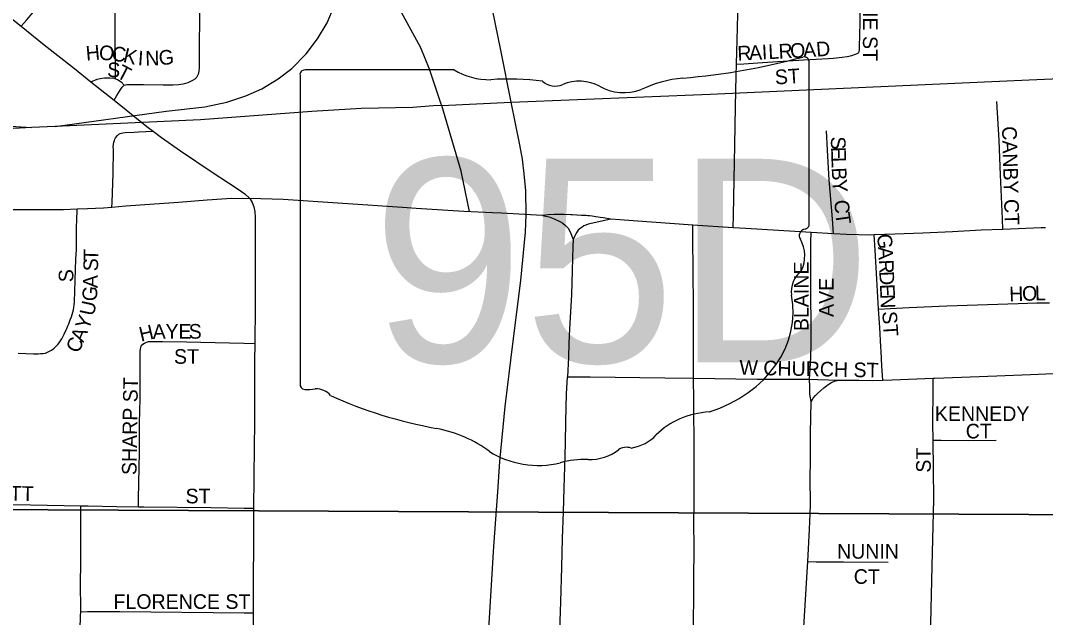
# Model space of a CAD drawing. Extents: x -9.1 to 34, y -3.1 to 22.
# Drawn here: x 4.437 to 5.101, y 19.706 to 20.093 of the extents above; entities that cross this region are included whole.
import ezdxf

# ---------------------------------------------------------------- set-up
doc = ezdxf.new("R2010")
doc.units = 0
for name, color, linetype in [('GM_X_City_Street', 7, 'Continuous'), ('GM_X_City_Street_Text', 7, 'Continuous'), ('GM_X_Rail_Line', 7, 'Continuous'), ('GM_X_Section', 7, 'Continuous'), ('GM_X_State_Location', 7, 'Continuous'), ('GM_X_State_Route', 7, 'Continuous'), ('GM_X_State_Shield', 7, 'Continuous')]:
    doc.layers.add(name, color=color, linetype=linetype)

msp = doc.modelspace()

# ---------------------------------------------------------------- linework, layer by layer
at = {"layer": 'GM_X_City_Street'}
for points in [[(4.49874, 20.05516), (4.4988, 20.05841), (4.49887, 20.0614), (4.49858, 20.08324), (4.49882, 20.11749), (4.499, 20.18602), (4.49938, 20.25459), (4.49955, 20.27638), (4.49959, 20.28149)], [(4.5514, 20.05627), (4.55222, 20.05754), (4.55273, 20.05884), (4.55302, 20.06023), (4.55314, 20.06211), (4.55321, 20.06449), (4.55321, 20.06828), (4.55329, 20.07756), (4.55336, 20.09304), (4.55365, 20.12694), (4.55371, 20.15158), (4.55374, 20.17483), (4.55381, 20.2012), (4.55388, 20.22423), (4.55393, 20.24258), (4.55398, 20.25718), (4.55403, 20.27252), (4.55406, 20.28039)], [(4.4377, 20.08918), (4.44141, 20.09336), (4.44584, 20.09857), (4.44801, 20.10125), (4.4496, 20.10326), (4.45032, 20.10424), (4.45095, 20.10527), (4.45151, 20.10661), (4.45187, 20.1081), (4.45213, 20.11007), (4.45227, 20.11208), (4.45238, 20.11518), (4.45218, 20.12445), (4.45221, 20.14299), (4.45209, 20.15844), (4.45209, 20.17698), (4.45237, 20.19552), (4.45234, 20.20788), (4.45239, 20.21714), (4.45234, 20.22331)], [(4.90088, 20.06455), (4.90141, 20.08805), (4.90184, 20.10654), (4.90227, 20.12594)], [(4.97985, 20.07208), (4.98005, 20.0723), (4.98016, 20.07257), (4.98022, 20.07285), (4.98033, 20.07384), (4.98045, 20.07584), (4.98084, 20.09149), (4.98078, 20.09461), (4.98088, 20.10402), (4.98088, 20.11974), (4.98088, 20.12615)], [(4.90088, 20.06455), (4.9056, 20.06485), (4.91766, 20.06563), (4.94412, 20.06735), (4.95231, 20.06783), (4.96028, 20.06834), (4.96356, 20.06856), (4.96928, 20.06914), (4.97242, 20.06965), (4.97536, 20.07032), (4.97788, 20.07113), (4.97894, 20.07157), (4.97948, 20.07184), (4.97985, 20.07208)], [(4.89865, 19.9587), (4.89882, 19.96686), (4.89927, 19.98977), (4.89972, 20.01233), (4.90022, 20.03699), (4.90062, 20.05718), (4.90088, 20.06455)], [(4.4829, 20.05327), (4.48694, 20.05486), (4.48897, 20.05536), (4.49165, 20.05568), (4.49525, 20.05581), (4.49779, 20.05549), (4.49874, 20.05516)], [(4.49795, 20.04136), (4.49976, 20.04439), (4.50186, 20.04788), (4.50318, 20.04978), (4.50451, 20.05106)], [(4.49874, 20.05516), (4.50014, 20.05467), (4.50242, 20.05315), (4.50451, 20.05106)], [(4.50451, 20.05106), (4.50611, 20.05137), (4.50864, 20.0515), (4.51137, 20.05144), (4.51687, 20.05146), (4.52959, 20.05131), (4.53619, 20.05132), (4.53957, 20.05151), (4.54267, 20.05196), (4.54439, 20.05237), (4.54585, 20.05277), (4.54759, 20.05351), (4.54889, 20.05424), (4.55032, 20.05522), (4.5514, 20.05627)], [(5.07313, 19.95761), (5.07289, 19.96456), (5.07257, 19.97405), (5.0716, 19.99301), (5.07076, 20.01514), (5.0694, 20.04044)], [(4.49882, 20.01683), (4.50008, 20.01845), (4.50097, 20.01924), (4.50195, 20.01976), (4.50359, 20.02013), (4.50499, 20.0203), (4.51087, 20.02062), (4.51368, 20.02075), (4.52329, 20.02122)], [(4.96364, 19.9548), (4.96287, 19.96441), (4.96084, 19.98979), (4.95962, 20.00885), (4.95896, 20.02155)], [(4.4965, 19.97212), (4.49661, 19.97498), (4.49733, 19.99375), (4.49742, 20.00946), (4.49741, 20.01101), (4.49756, 20.01258), (4.49782, 20.01421), (4.49808, 20.01525), (4.49834, 20.01609), (4.49882, 20.01683)], [(4.45746, 19.87949), (4.4589, 19.88059), (4.4603, 19.88178), (4.46139, 19.88298), (4.46232, 19.88409), (4.4632, 19.88535), (4.46409, 19.88674), (4.4656, 19.88971), (4.46687, 19.89249), (4.46729, 19.8935), (4.46803, 19.89521), (4.46854, 19.89645), (4.46905, 19.89772), (4.46955, 19.89906), (4.47027, 19.90104), (4.47069, 19.90249), (4.47118, 19.90405), (4.47157, 19.90561), (4.47187, 19.90706), (4.47214, 19.90877), (4.47229, 19.91062), (4.4732, 19.93835), (4.47358, 19.94451), (4.47366, 19.95996), (4.47376, 19.96305), (4.47404, 19.97087)], [(4.7753, 19.96664), (4.77956, 19.96565), (4.78267, 19.96448), (4.78644, 19.96282), (4.78832, 19.96172), (4.79021, 19.96025), (4.79179, 19.95838), (4.79307, 19.95601), (4.79505, 19.95098)], [(4.81951, 19.96433), (4.80472, 19.96095), (4.80328, 19.96044), (4.80205, 19.95996), (4.80087, 19.95917), (4.79958, 19.95818), (4.7984, 19.9571), (4.79742, 19.95581), (4.79653, 19.95433), (4.79584, 19.95295), (4.79505, 19.95098)], [(4.87298, 19.90525), (4.87297, 19.90841), (4.87255, 19.95228), (4.87247, 19.96031)], [(4.79505, 19.95098), (4.79487, 19.94665), (4.79448, 19.93093), (4.79389, 19.91524), (4.79279, 19.89328), (4.79235, 19.88384), (4.79196, 19.87456), (4.79138, 19.86205)], [(4.94809, 19.86072), (4.94878, 19.87074), (4.94892, 19.87491), (4.9492, 19.88357), (4.94917, 19.88665), (4.94891, 19.92407), (4.949, 19.94932), (4.94902, 19.95567)], [(4.99274, 19.90598), (4.99153, 19.9254), (4.99051, 19.94411), (4.98996, 19.95402)], [(4.87294, 19.8612), (4.87306, 19.87726), (4.87298, 19.90525)], [(4.99274, 19.90598), (5.00021, 19.90641), (5.01245, 19.90712), (5.03697, 19.90804), (5.08306, 19.90961), (5.09523, 19.90999), (5.10347, 19.91014)], [(4.99547, 19.86005), (4.99529, 19.8631), (4.99492, 19.86934), (4.99444, 19.87852), (4.99426, 19.88158), (4.99348, 19.89402), (4.99274, 19.90598)], [(4.51553, 19.88206), (4.51654, 19.88322), (4.51762, 19.88399), (4.51886, 19.88454), (4.5201, 19.88492), (4.52126, 19.88508), (4.52281, 19.88506), (4.52482, 19.88504), (4.52915, 19.885), (4.54484, 19.88487), (4.56339, 19.88445), (4.58194, 19.88399), (4.58892, 19.88383)], [(4.43592, 19.87741), (4.44582, 19.87712), (4.44887, 19.8771), (4.45033, 19.87715), (4.45191, 19.87728), (4.45343, 19.87754), (4.45483, 19.87803), (4.45618, 19.87867), (4.45746, 19.87949)], [(4.51371, 19.778), (4.5138, 19.78312), (4.51431, 19.81354), (4.51435, 19.81671), (4.5144, 19.81977), (4.51436, 19.82894), (4.51446, 19.83181), (4.51446, 19.83468), (4.51454, 19.8377), (4.51485, 19.85019), (4.51482, 19.87485), (4.51482, 19.87617), (4.51484, 19.87826), (4.51507, 19.8802), (4.51553, 19.88206)], [(4.78619, 19.68761), (4.78632, 19.69165), (4.78706, 19.71644), (4.78765, 19.73881), (4.78821, 19.75737), (4.78874, 19.77472), (4.7892, 19.79012), (4.78961, 19.80392), (4.79002, 19.81913), (4.79039, 19.83313), (4.79084, 19.85111), (4.79138, 19.86205)], [(4.79138, 19.86205), (4.80615, 19.86216), (4.85438, 19.86139), (4.87294, 19.8612)], [(4.87294, 19.8612), (4.91413, 19.86066), (4.94599, 19.86072), (4.94809, 19.86072)], [(4.87302, 19.69196), (4.87302, 19.6932), (4.87323, 19.73032), (4.87331, 19.752), (4.87324, 19.76754), (4.87343, 19.77996), (4.87337, 19.78602), (4.87349, 19.81334), (4.87311, 19.84699), (4.87294, 19.8612)], [(4.94809, 19.86072), (4.9534, 19.86048), (4.96708, 19.86003)], [(4.9492, 19.84603), (4.94863, 19.84861), (4.94834, 19.85098), (4.94822, 19.85565), (4.94809, 19.86072)], [(5.02799, 19.82108), (5.02793, 19.83222), (5.02804, 19.85377), (5.02807, 19.86123)], [(5.02624, 19.68796), (5.0266, 19.70234), (5.02747, 19.73956), (5.02846, 19.78295), (5.02799, 19.82108)], [(5.02799, 19.82108), (5.03331, 19.82104), (5.0512, 19.82088), (5.06887, 19.82114)], [(4.36566, 19.78066), (4.38924, 19.78031), (4.41939, 19.77962), (4.44389, 19.77921), (4.47645, 19.7787)], [(4.47629, 19.70998), (4.4764, 19.71677), (4.47619, 19.72297), (4.47622, 19.73232), (4.47643, 19.73747), (4.47634, 19.74164), (4.4763, 19.76335), (4.47637, 19.76957), (4.47645, 19.7787)], [(4.47645, 19.7787), (4.48105, 19.77864), (4.49937, 19.77826), (4.51371, 19.778)], [(4.51371, 19.778), (4.51726, 19.77793), (4.56053, 19.77749), (4.58219, 19.77715), (4.58822, 19.77706)], [(4.94687, 19.74247), (4.9524, 19.74243), (4.97004, 19.74233), (4.99886, 19.7422)], [(4.47586, 19.68608), (4.4759, 19.69213), (4.47604, 19.69844), (4.47625, 19.70744), (4.47629, 19.70998)], [(4.47629, 19.70998), (4.48072, 19.71009), (4.48979, 19.71013), (4.50163, 19.7101), (4.58211, 19.70938), (4.58788, 19.70933)]]:
    msp.add_lwpolyline(points, dxfattribs=at)
at = {"layer": 'GM_X_Rail_Line'}
for points in [[(4.75491, 20.03998), (4.74815, 20.07376), (4.74114, 20.10871), (4.73789, 20.12443), (4.7349, 20.14029), (4.73321, 20.15172), (4.73217, 20.1612), (4.73113, 20.17329), (4.73074, 20.18758), (4.73087, 20.20382), (4.73178, 20.27568), (4.73412, 20.38846), (4.73899, 20.64696), (4.73945, 20.75234), (4.7401, 20.80691), (4.74107, 20.89157), (4.74116, 20.9)], [(4.4598, 20.02426), (4.53171, 20.0341), (4.55655, 20.03704), (4.57092, 20.04007), (4.58325, 20.04408), (4.59361, 20.04868), (4.60417, 20.05513), (4.61298, 20.06178), (4.62217, 20.07136), (4.6295, 20.08095), (4.63576, 20.09141), (4.64036, 20.10217), (4.64339, 20.11156), (4.64564, 20.12349), (4.64613, 20.13796), (4.64525, 20.14872), (4.64251, 20.16368), (4.6386, 20.17366), (4.634, 20.18373), (4.62911, 20.19263), (4.61029, 20.22782), (4.54232, 20.35069), (4.53176, 20.37042), (4.5167, 20.4033)], [(4.7097, 20.03871), (4.70209, 20.06128), (4.69638, 20.07528), (4.61143, 20.2311)], [(2.6, 20.20616), (2.61878, 20.20477), (2.65021, 20.20366), (2.67105, 20.20276), (2.70793, 20.19875), (3.62422, 20.09412), (3.99829, 20.05166), (4.19407, 20.02982), (4.21899, 20.02788), (4.24227, 20.02625), (4.29308, 20.02562), (4.35791, 20.026), (4.38531, 20.02687), (4.40008, 20.0265), (4.44452, 20.02352)], [(4.75491, 20.03998), (4.88383, 20.04522), (5.08049, 20.05405), (5.19819, 20.05912), (5.37213, 20.0668), (5.43128, 20.06935)], [(4.7044, 20.03755), (4.69135, 20.03665), (4.6579, 20.03587), (4.62581, 20.03402), (4.55375, 20.02867), (4.4598, 20.02426)], [(4.70996, 20.03794), (4.7044, 20.03755)], [(4.70996, 20.03794), (4.7097, 20.03871)], [(4.70996, 20.03794), (4.75491, 20.03998)], [(4.72803, 19.9692), (4.72264, 19.9953), (4.70996, 20.03794)], [(4.76465, 19.96727), (4.76452, 19.98255), (4.76336, 19.99359), (4.76219, 20.0032), (4.76063, 20.01243), (4.75491, 20.03998)], [(4.4598, 20.02426), (4.44452, 20.02352)], [(4.44452, 20.02352), (4.42483, 20.02258)], [(4.78778, 19.09094), (4.76193, 19.17487), (4.7375, 19.25556), (4.73373, 19.26843), (4.73113, 19.27856), (4.7284, 19.29065), (4.72658, 19.30156), (4.7245, 19.31481), (4.7236, 19.32365), (4.72241, 19.33388), (4.72204, 19.3499), (4.72178, 19.36367), (4.7223, 19.37848), (4.72399, 19.41031), (4.73308, 19.56935), (4.73945, 19.68097), (4.74361, 19.75217), (4.7462, 19.78777), (4.74763, 19.80726), (4.75114, 19.843), (4.75595, 19.88354), (4.76128, 19.92446), (4.76426, 19.95591), (4.76465, 19.96727)]]:
    msp.add_lwpolyline(points, dxfattribs=at)
at = {"layer": 'GM_X_Section'}
for points in [[(4.22892, 20.78268), (5.2279, 20.77322), (5.226, 19.77229), (4.2285, 19.77719)], [(4.2285, 19.77719), (5.226, 19.77229), (5.22068, 18.771), (4.22542, 18.77097)]]:
    msp.add_lwpolyline(points, close=True, dxfattribs=at)
at = {"layer": 'GM_X_State_Route'}
for points in [[(4.23107, 20.25518), (4.25901, 20.23288), (4.29774, 20.20173), (4.35591, 20.15507), (4.37889, 20.13658), (4.414, 20.10833), (4.4377, 20.08918), (4.45266, 20.07709), (4.47222, 20.06172), (4.4829, 20.05327), (4.49795, 20.04136), (4.50576, 20.03497), (4.51271, 20.02947), (4.52002, 20.0237), (4.52329, 20.02122), (4.52859, 20.01721), (4.541, 20.00846), (4.56139, 19.9947), (4.57197, 19.98778), (4.57827, 19.98368), (4.58251, 19.98056), (4.58588, 19.97764)], [(4.3665, 19.97125), (4.3675, 19.97124), (4.37512, 19.97115), (4.43089, 19.97052), (4.43696, 19.9705), (4.44585, 19.97047), (4.46523, 19.97051), (4.47404, 19.97087), (4.48078, 19.97116), (4.49113, 19.97166), (4.4965, 19.97212), (4.50558, 19.9729), (4.53965, 19.97525), (4.55824, 19.97671), (4.57384, 19.97787), (4.58588, 19.97764)], [(4.58588, 19.97764), (4.58734, 19.97496), (4.58841, 19.97222), (4.589, 19.96915), (4.58926, 19.9653), (4.58925, 19.9584), (4.58924, 19.94675), (4.58917, 19.9065), (4.58893, 19.8848), (4.58892, 19.88383), (4.58875, 19.87237), (4.5888, 19.86936), (4.58878, 19.86134), (4.58876, 19.84897), (4.58875, 19.83996), (4.58874, 19.83233), (4.58851, 19.81686), (4.58822, 19.77706), (4.58813, 19.76405), (4.58793, 19.72073), (4.58788, 19.70933), (4.58787, 19.70518), (4.58772, 19.68235)], [(4.68457, 19.97176), (4.60739, 19.97688), (4.58588, 19.97764)], [(4.79445, 19.96699), (4.79347, 19.96703), (4.78915, 19.9672), (4.78278, 19.9672), (4.77884, 19.96697), (4.7753, 19.96664), (4.76755, 19.96706), (4.74865, 19.96808), (4.74282, 19.96826), (4.72433, 19.96924), (4.69354, 19.97117), (4.68457, 19.97176)], [(5.10086, 19.95871), (5.09809, 19.95866), (5.07313, 19.95761), (5.05922, 19.95702), (5.04061, 19.95598), (5.02149, 19.95515), (5.00321, 19.95446), (4.98996, 19.95402), (4.98762, 19.95394), (4.97198, 19.9543), (4.96364, 19.9548), (4.94902, 19.95567), (4.90682, 19.95819), (4.89865, 19.9587), (4.87247, 19.96031), (4.8338, 19.96314), (4.82527, 19.96377), (4.81951, 19.96433), (4.81458, 19.96505), (4.81253, 19.96543), (4.80981, 19.9658), (4.80736, 19.96614), (4.80565, 19.96634), (4.80459, 19.96646), (4.80322, 19.9666), (4.80056, 19.96671), (4.79445, 19.96699)], [(4.96708, 19.86003), (4.96844, 19.85993), (4.98007, 19.8599), (4.98913, 19.85984), (4.99547, 19.86005), (5.00153, 19.86024), (5.02807, 19.86123), (5.02924, 19.86127), (5.06928, 19.86271), (5.09104, 19.86356), (5.10596, 19.86424), (5.12191, 19.86496), (5.18634, 19.86778), (5.19618, 19.86822), (5.21393, 19.86893), (5.27092, 19.87124), (5.27826, 19.87168)], [(4.9492, 19.84603), (4.9505, 19.84825), (4.95192, 19.85014), (4.95317, 19.8513), (4.95546, 19.85326), (4.95733, 19.85495), (4.95906, 19.85637), (4.96011, 19.8571), (4.96091, 19.85765), (4.9619, 19.85826), (4.96322, 19.85892), (4.96492, 19.85959), (4.96708, 19.86003)], [(4.94515, 19.6888), (4.94459, 19.69187), (4.94429, 19.69443), (4.94421, 19.69656), (4.94687, 19.74247), (4.94807, 19.76318), (4.94862, 19.77878), (4.9484, 19.79752), (4.94862, 19.80683), (4.94861, 19.82556), (4.9492, 19.84603)]]:
    msp.add_lwpolyline(points, dxfattribs=at)
at = {"layer": 'GM_X_State_Shield'}
for p, q in [((4.94787, 19.96123), (4.94787, 20.06592)), ((4.61828, 20.05752), (4.61828, 19.8574)), ((4.71805, 20.06096), (4.62153, 20.06096)), ((4.94783, 19.96126), (4.94787, 19.96123))]:
    msp.add_line(p, q, dxfattribs=at)
for centre, major_axis, start_param, end_param in [((4.83046, 20.33379), (0.34952, 0), 4.814394, 5.042369), ((4.94421, 20.06635), (0.00367, 0), 6.141152, 7.989035), ((4.62206, 20.05794), (0.00382, 0), 1.712693, 3.28349), ((4.74103, 20.08419), (0.03703, 0), 4.042523, 4.731795), ((4.75331, 19.94861), (0.13295, 0), 1.404758, 1.657858), ((4.7835, 20.05898), (0.01068, 0), 3.836095, 5.185415), ((4.79918, 20.03585), (0.02221, 0), 0.950623, 2.079405), ((4.82785, 20.06757), (0.02672, 0), 4.081561, 5.145723), ((4.87505, 19.99984), (0.07032, 0), 1.699011, 2.107814), ((4.94702, 19.95355), (0.00568, 0), 1.883978, 3.671073), ((4.94395, 19.96083), (0.00393, 0), 5.05454, 6.418171), ((4.91089, 19.94031), (0.03409, 0), 5.934695, 6.695948), ((4.96101, 19.91742), (0.0248, 0), 2.387724, 3.262537), ((4.85004, 19.90411), (0.08742, 0), 5.101752, 6.440018), ((4.62209, 19.85696), (0.00385, 0), 3.00124, 4.508301), ((4.62268, 19.87743), (0.0294, 0), 4.665946, 4.897461), ((4.62869, 19.84585), (0.0106, 0), 0.519207, 1.627899), ((4.76252, 20.02565), (0.2524, 0), 4.195997, 4.488961), ((4.8869, 19.80121), (0.04788, 0), 1.647645, 2.488434), ((4.68727, 19.76749), (0.07897, 0), 0.823519, 1.323587), ((4.82624, 19.838), (0.02824, 0), 4.937069, 5.64225), ((4.77268, 19.84486), (0.05011, 0), 4.026481, 4.996735), ((4.80529, 19.82987), (0.0267, 0), 4.691044, 5.507374), ((4.82945, 19.81049), (0.00752, 0), 1.147584, 2.315152), ((4.80163, 19.77567), (0.04118, 0), 1.495662, 1.94098)]:
    msp.add_ellipse(centre, major_axis=major_axis, ratio=0.8, start_param=start_param, end_param=end_param, dxfattribs=at)

# ---------------------------------------------------------------- texts
at = {"layer": 'GM_X_City_Street_Text'}
for s, height, rotation, p in [('ERIE ST', 0.00947, 270, (4.98263, 20.11592)), ('H', 0.00947, 5.09944, (4.47999, 20.06686)), ('O', 0.00947, 355.29625, (4.48786, 20.0676)), ('A', 0.00947, 2.83454, (4.90909, 20.06724)), ('I', 0.00947, 2.84276, (4.91741, 20.06765)), ('L', 0.00947, 2.81466, (4.92157, 20.06786)), ('R', 0.00947, 2.83186, (4.92823, 20.06818)), ('O', 0.00947, 2.82093, (4.93572, 20.06856)), ('A', 0.00947, 3.17297, (4.94411, 20.06897)), ('D', 0.00947, 4.83643, (4.95273, 20.06945)), ('C', 0.00947, 353.60082, (4.49609, 20.06692)), ('K', 0.00947, 346.40905, (4.50324, 20.06614)), ('I', 0.00947, 356.02956, (4.51305, 20.06392)), ('N', 0.00947, 1.50299, (4.51819, 20.06361)), ('G', 0.00947, 5.48292, (4.52724, 20.06387)), ('R', 0.00947, 2.81874, (4.90159, 20.06687)), ('S', 0.00947, 357.07482, (4.49322, 20.05642)), ('T', 0.00947, 332.66519, (4.49885, 20.05635)), ('ST', 0.00947, 3.57463, (4.92592, 20.05144)), ('CANBY CT', 0.00947, 271.63302, (5.07263, 20.0243)), ('S', 0.00947, 271.77627, (4.96179, 20.01764)), ('E', 0.00947, 271.74896, (4.962, 20.01098)), ('L', 0.00947, 271.76405, (4.9622, 20.00431)), ('B', 0.00947, 272.35658, (4.96241, 19.99754)), ('Y', 0.00947, 274.71212, (4.96275, 19.98962)), ('C', 0.00947, 271.23851, (4.96429, 19.9767)), ('T', 0.00947, 278.1383, (4.96456, 19.96796)), ('G', 0.00947, 274.55127, (4.99179, 19.95441)), ('T', 0.00947, 88.72654, (4.48761, 19.93709)), ('A', 0.00947, 273.17135, (4.99244, 19.94617)), ('S', 0.00947, 88.71603, (4.48746, 19.93042)), ('S', 0.00947, 90, (4.47156, 19.92342)), ('BLAINE', 0.00947, 90, (4.9474, 19.89176)), ('R', 0.00947, 272.52648, (4.9929, 19.93788)), ('A', 0.00947, 88.56277, (4.48719, 19.91956)), ('AVE', 0.00947, 90, (4.96369, 19.90092)), ('D', 0.00947, 272.49241, (4.99323, 19.93039)), ('G', 0.00947, 86.63738, (4.48669, 19.91089)), ('E', 0.00947, 272.48719, (4.9936, 19.92206)), ('H', 0.00947, 1.88003, (5.07746, 19.91104)), ('O', 0.00947, 1.85818, (5.08578, 19.91131)), ('L', 0.00947, 1.97718, (5.09413, 19.91158)), ('U', 0.00947, 77.74136, (4.48471, 19.90116)), ('N', 0.00947, 272.47057, (4.99388, 19.9154)), ('Y', 0.00947, 69.27153, (4.48132, 19.8919)), ('ST', 0.00947, 273.57465, (4.99512, 19.90437)), ('A', 0.00947, 67.32, (4.47798, 19.88388)), ('H', 0.00947, 13.25178, (4.51534, 19.88481)), ('A', 0.00947, 1.46432, (4.52294, 19.88666)), ('Y', 0.00947, 0.00001, (4.53121, 19.88687)), ('E', 0.00947, 0.00001, (4.53954, 19.88687)), ('S', 0.00947, 0.00001, (4.5462, 19.88687)), ('C', 0.00947, 67.07564, (4.47504, 19.87693)), ('ST', 0.00947, 0.00001, (4.53668, 19.87058)), ('W CHURCH ST', 0.0094697, 358.81516, (4.9026, 19.86354)), ('SHARP ST', 0.00947, 89.13129, (4.5124, 19.79846)), ('KENNEDY', 0.00947, 0.00001, (5.02918, 19.83354)), ('CT', 0.00947, 0.00001, (5.04918, 19.82225)), ('ST', 0.00947, 90, (5.02656, 19.80009)), ('BENNETT', 0.00947, 359.08765, (4.38671, 19.7827)), ('ST', 0.00947, 0.00001, (4.54418, 19.7802)), ('NUNIN', 0.00947, 0.00001, (4.96585, 19.74437)), ('CT', 0.00947, 0.00001, (4.97668, 19.72808)), ('FLORENCE ST', 0.0094697, 0.00001, (4.49751, 19.71187))]:
    msp.add_text(s, height=height, rotation=rotation, dxfattribs=at).set_placement(p)
at = {"layer": 'GM_X_State_Location'}
for s in ['s', 'r']:
    msp.add_text(s, height=0.000189, dxfattribs=at).set_placement((4.77937, 19.94415))
msp.add_text('95D', height=0.000189, rotation=0.00001, dxfattribs=at).set_placement((4.70668, 19.93037))
at = {"layer": 'GM_X_State_Shield'}
msp.add_text('95D', height=0.131836, dxfattribs=at).set_placement((4.66502, 19.87151))

doc.saveas('drawing.dxf')
